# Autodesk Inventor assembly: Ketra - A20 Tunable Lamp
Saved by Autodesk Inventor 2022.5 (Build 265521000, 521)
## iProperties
Created: 2024-07
Part Number: Ketra - A20 Tunable Lamp
Document SubType Name: Assembly
Designer: AdminForWorker
Title: Ketra - A20 Tunable Lamp v4
Author: AdminForWorker
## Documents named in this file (2)
- z:\worker\convert-fusion-r03-cosv3\tmp\job-1\6\temp\files\4192786e-9465-4c09-abb0-424b8e2f5858\Ketra - A20 Tunable Lamp v4.iam
- z:\worker\convert-fusion-r03-cosv3\tmp\job-1\6\temp\files\4192786e-9465-4c09-abb0-424b8e2f5858\Ketra A20.ipt
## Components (1 placed, 1 different names)
1. Ketra A20:1
